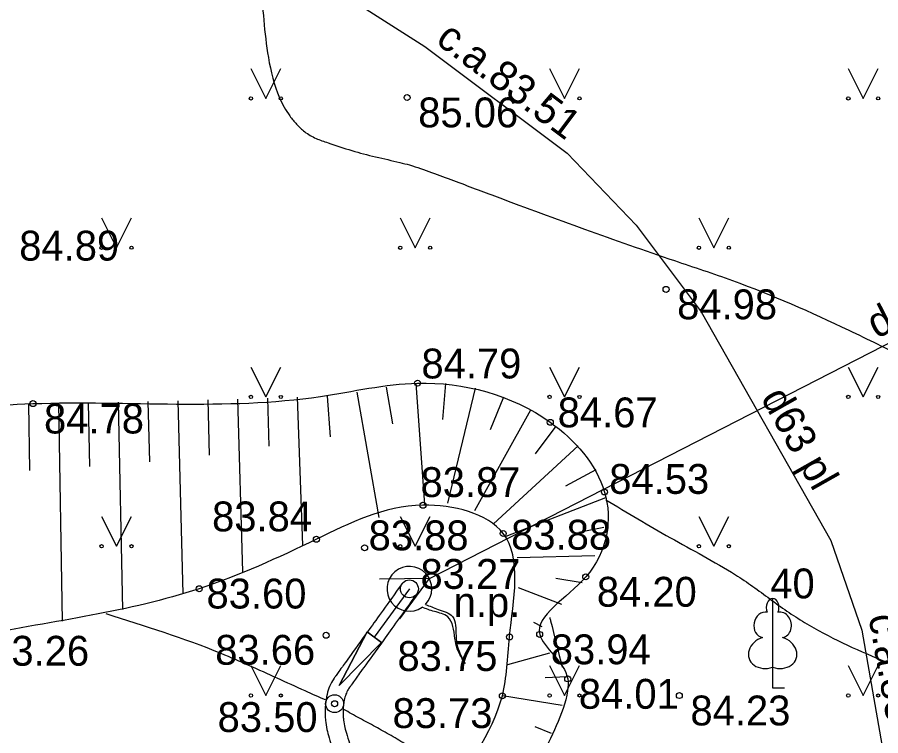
# Model space of a CAD drawing. Extents: x 576692 to 577659, y 273254 to 273799.
# Drawn here: x 576845.84 to 576860.29, y 273619.33 to 273631.36 of the extents above; entities that cross this region are included whole.
import ezdxf

# ---------------------------------------------------------------- set-up
doc = ezdxf.new("R2010")
doc.units = 0
for name, color, linetype in [('APGR_SARK_####_####_#', 7, 'Continuous'), ('BUVE_EKAS_ADRS_TKST_#', 7, 'Continuous'), ('ELEK_STTP_####_TKST_#', 7, 'Continuous'), ('GAZE_ELEM_####_####_#', 7, 'Continuous'), ('GAZE_VADP_VSP2_TKST_#', 7, 'Continuous'), ('GEOD_ELEM_####_TKST_#', 7, 'Continuous'), ('GEOD_SITP_####_TKST_#', 7, 'Continuous'), ('HIDT_REZV_####_TKST_#', 7, 'Continuous'), ('Level 50', 7, 'Continuous'), ('LKAN_ELEM_PAST_TKST_#', 7, 'Continuous'), ('LKAN_VADP_PAST_####_I', 7, 'Continuous'), ('NORB_ZOGS_ZSTP_####_#', 7, 'Continuous'), ('RELJ_ELEM_####_####_#', 7, 'Continuous'), ('SAKT_ELEM_####_####_#', 7, 'Continuous'), ('TERT_IZMT_####_TKST_#', 7, 'Continuous'), ('UDTK_VADP_UDEN_####_#', 7, 'Continuous')]:
    doc.layers.add(name, color=color, linetype=linetype)

msp = doc.modelspace()

# ---------------------------------------------------------------- linework, layer by layer
at = {"layer": 'BUVE_EKAS_ADRS_TKST_#'}
for p, q in [((576852.402, 273621.786), (576851.815, 273620.976)), ((576852.614, 273621.477), (576852.614, 273621.477)), ((576852.614, 273621.477), (576852.614, 273621.477)), ((576851.228, 273620.167), (576851.694, 273621.065)), ((576851.694, 273621.065), (576851.936, 273620.888)), ((576851.936, 273620.888), (576851.228, 273620.167))]:
    msp.add_line(p, q, dxfattribs=at)
msp.add_lwpolyline([(576851.815, 273620.976), (576851.694, 273621.065), (576851.228, 273620.167), (576851.936, 273620.888), (576851.815, 273620.976)], dxfattribs=at)
for centre in [(576852.402, 273621.786), (576851.15, 273619.863)]:
    msp.add_circle(centre, 0.15, dxfattribs=at)
msp.add_arc((576852.402, 273621.786), 0.375, 316.079, 304.6674, dxfattribs=at)
for points in [[(576852.671, 273621.525), (576852.885, 273621.443), (576853.124, 273621.323), (576853.183, 273620.998), (576853.209, 273620.815), (576853.337, 273620.537)], [(576853.337, 273620.537), (576853.204, 273620.783), (576853.165, 273620.957), (576853.044, 273621.317), (576852.821, 273621.407), (576852.614, 273621.477)]]:
    msp.add_spline(points, degree=3, dxfattribs=at)
at = {"layer": 'GAZE_ELEM_####_####_#'}
for p, q in [((576852.013, 273625.165), (576852.122, 273624.552)), ((576852.509, 273625.229), (576852.656, 273623.192)), ((576853.008, 273625.226), (576852.957, 273624.625)), ((576853.501, 273625.147), (576853.039, 273623.222)), ((576850.525, 273624.995), (576850.61, 273622.52)), ((576851.025, 273625.015), (576851.076, 273624.334)), ((576851.521, 273625.078), (576851.893, 273622.982)), ((576853.977, 273624.994), (576853.756, 273624.452)), ((576846.027, 273624.887), (576846.041, 273623.767)), ((576846.527, 273624.895), (576846.588, 273621.244)), ((576847.027, 273624.904), (576847.047, 273623.834)), ((576847.526, 273624.914), (576847.598, 273621.44)), ((576848.026, 273624.925), (576848.049, 273623.915)), ((576848.526, 273624.937), (576848.61, 273621.701)), ((576849.026, 273624.95), (576849.05, 273624.025)), ((576849.526, 273624.964), (576849.607, 273622.073)), ((576850.026, 273624.979), (576850.051, 273624.175)), ((576854.428, 273624.779), (576853.493, 273623.092)), ((576854.851, 273624.513), (576854.509, 273624.045)), ((576855.227, 273624.184), (576853.809, 273622.875)), ((576855.521, 273623.781), (576855.013, 273623.504)), ((576855.687, 273623.312), (576854.015, 273622.664)), ((576855.657, 273622.816), (576855.236, 273622.729)), ((576855.507, 273622.339), (576854.209, 273622.304)), ((576855.296, 273621.887), (576854.855, 273621.961)), ((576854.953, 273621.525), (576854.231, 273621.801)), ((576854.626, 273621.149), (576854.483, 273621.223)), ((576854.747, 273620.709), (576854.042, 273620.511)), ((576855.046, 273620.315), (576854.677, 273620.295)), ((576854.959, 273619.833), (576853.958, 273619.995)), ((576854.781, 273619.366), (576854.507, 273619.473))]:
    msp.add_line(p, q, dxfattribs=at)
msp.add_spline([(576832.752, 273667.765), (576832.509, 273663.16), (576832.58, 273657.617), (576832.99, 273656.888), (576834.178, 273656.214), (576834.728, 273652.581), (576835.768, 273647.802), (576835.442, 273646.054), (576836.91, 273644.618), (576839.764, 273638.662), (576839.933, 273637.528), (576840.475, 273632.274), (576842.148, 273628.271), (576842.73, 273626.244), (576843.067, 273625.31), (576843.946, 273624.925), (576846.1, 273624.888), (576850.915, 273625.009), (576852.538, 273625.231), (576854.761, 273624.575), (576855.668, 273623.408), (576855.354, 273621.987), (576854.583, 273621.023), (576855.053, 273620.278), (576855.05, 273620.08), (576854.604, 273618.921), (576854.165, 273617.889), (576853.774, 273617.488), (576853.674, 273617.252), (576853.77, 273616.967), (576854.827, 273616.356), (576854.95, 273616.221), (576855.722, 273614.848), (576857.549, 273612.349), (576858.206, 273610.078), (576857.63, 273607.292), (576856.966, 273605.786), (576854.948, 273601.016)], degree=3, dxfattribs=at)
at = {"layer": 'GAZE_VADP_VSP2_TKST_#'}
msp.add_lwpolyline([(576836.372, 273653.396), (576836.519, 273652.953), (576837.582, 273650.133), (576837.906, 273649.009), (576838.095, 273648.207), (576839.874, 273643.493), (576841.093, 273641.261), (576843.166, 273638.464), (576845.597, 273635.684), (576846.78, 273634.715), (576850.695, 273632.125), (576852.662, 273630.867), (576855.046, 273629.082), (576856.199, 273627.876), (576857.289, 273626.424), (576859.457, 273622.595), (576859.975, 273621.094), (576860.513, 273618.031), (576860.503, 273617.465), (576860.358, 273616.452), (576860.419, 273615.51), (576860.941, 273611.653), (576861.574, 273601.614), (576861.576, 273595.267)], dxfattribs=at)
at = {"layer": 'GEOD_ELEM_####_TKST_#'}
msp.add_spline([(576854.751, 273621.305), (576854.765, 273621.25), (576854.96, 273620.473)], degree=3, dxfattribs=at)
at = {"layer": 'GEOD_SITP_####_TKST_#'}
for points in [[(576836.737, 273653.507), (576837.199, 273653.071), (576838.168, 273651.964), (576839.276, 273650.389), (576839.675, 273649.775), (576840.068, 273649.157), (576840.874, 273647.935), (576842.937, 273645.043), (576843.644, 273644.077), (576844.358, 273643.116), (576845.071, 273642.154), (576845.776, 273641.185), (576846.532, 273639.939), (576848.959, 273635.068), (576849.467, 273633.911), (576849.494, 273633.87), (576849.54, 273633.844), (576849.669, 273633.76), (576849.716, 273633.696), (576849.75, 273633.628), (576849.789, 273633.484), (576849.818, 273633.184), (576849.885, 273632.56), (576849.923, 273631.934), (576849.964, 273631.308), (576850.042, 273630.684), (576850.228, 273630.011), (576850.401, 273629.706), (576850.514, 273629.568), (576850.649, 273629.442), (576850.839, 273629.33), (576851.04, 273629.256), (576851.437, 273629.127), (576852.241, 273628.927), (576852.405, 273628.885), (576852.774, 273628.757), (576853.14, 273628.623), (576853.871, 273628.35), (576855.336, 273627.811), (576856.838, 273627.284), (576857.811, 273626.95), (576859.757, 273626.119), (576860.71, 273625.654), (576861.662, 273625.19), (576862.208, 273624.916), (576862.747, 273624.63), (576863.288, 273624.343), (576863.84, 273624.071), (576864.734, 273623.812), (576865.684, 273623.739), (576866.647, 273623.686), (576867.118, 273623.618), (576867.35, 273623.56), (576867.582, 273623.491), (576867.793, 273623.35), (576869.286, 273620.101), (576869.949, 273618.673), (576870.065, 273618.383)], [(576855.69, 273623.279), (576856.771, 273622.643), (576857.319, 273622.34), (576857.859, 273622.023), (576858.151, 273621.827), (576858.436, 273621.619), (576858.722, 273621.414), (576859.019, 273621.223), (576860.313, 273620.593), (576861.378, 273620.176), (576862.149, 273619.833), (576862.903, 273619.459), (576863.642, 273619.051), (576864.37, 273618.606), (576864.715, 273618.279), (576865.665, 273616.764), (576866.071, 273615.581), (576866.112, 273615.391), (576866.295, 273615.092), (576866.625, 273614.961), (576867.386, 273614.691), (576867.79, 273614.462), (576868.144, 273614.156), (576868.694, 273613.398)], [(576850.996, 273619.925), (576850.659, 273620.076), (576850.191, 273620.288), (576849.253, 273620.702), (576847.324, 273621.365)], [(576853.147, 273618.43), (576852.951, 273618.676), (576852.725, 273618.9), (576852.605, 273618.996), (576852.483, 273619.087), (576852.357, 273619.172), (576852.228, 273619.252), (576851.965, 273619.403), (576851.699, 273619.548), (576851.434, 273619.693), (576851.305, 273619.766)]]:
    msp.add_spline(points, degree=3, dxfattribs=at)
at = {"layer": 'Level 50'}
msp.add_lwpolyline([(576852.738, 273621.958), (576869.063, 273630.326), (576880.368, 273635.749)], dxfattribs=at)
at = {"layer": 'LKAN_ELEM_PAST_TKST_#'}
for p, q in [((576849.75, 273630.5), (576850, 273630)), ((576850, 273630), (576850.25, 273630.5)), ((576854.75, 273630.5), (576855, 273630)), ((576855, 273630), (576855.25, 273630.5)), ((576859.75, 273630.5), (576860, 273630)), ((576860, 273630), (576860.25, 273630.5)), ((576847.25, 273628), (576847.5, 273627.5)), ((576847.5, 273627.5), (576847.75, 273628)), ((576852.25, 273628), (576852.5, 273627.5)), ((576852.5, 273627.5), (576852.75, 273628)), ((576857.25, 273628), (576857.5, 273627.5)), ((576857.5, 273627.5), (576857.75, 273628)), ((576849.75, 273625.5), (576850, 273625)), ((576850, 273625), (576850.25, 273625.5)), ((576854.75, 273625.5), (576855, 273625)), ((576855, 273625), (576855.25, 273625.5)), ((576859.75, 273625.5), (576860, 273625)), ((576860, 273625), (576860.25, 273625.5)), ((576847.25, 273623), (576847.5, 273622.5)), ((576847.5, 273622.5), (576847.75, 273623)), ((576852.25, 273623), (576852.5, 273622.5)), ((576852.5, 273622.5), (576852.75, 273623)), ((576857.25, 273623), (576857.5, 273622.5)), ((576857.5, 273622.5), (576857.75, 273623)), ((576849.75, 273620.5), (576850, 273620)), ((576850, 273620), (576850.25, 273620.5)), ((576854.75, 273620.5), (576855, 273620)), ((576855, 273620), (576855.25, 273620.5)), ((576858.483, 273620.474), (576858.483, 273620.127)), ((576859.75, 273620.5), (576860, 273620)), ((576860, 273620), (576860.25, 273620.5)), ((576858.483, 273620.127), (576858.683, 273620.127))]:
    msp.add_line(p, q, dxfattribs=at)
for points in [[(576858.483, 273621.627), (576858.483, 273620.474)], [(576858.573, 273621.395), (576858.572, 273621.396)]]:
    msp.add_lwpolyline(points, dxfattribs=at)
for centre, radius in [((576849.75, 273630), 0.028), ((576850.25, 273630), 0.0263), ((576854.75, 273630), 0.028), ((576855.25, 273630), 0.0263), ((576859.75, 273630), 0.028), ((576860.25, 273630), 0.0263), ((576847.25, 273627.5), 0.028), ((576847.75, 273627.5), 0.0263), ((576852.25, 273627.5), 0.028), ((576852.75, 273627.5), 0.0263), ((576857.25, 273627.5), 0.028), ((576857.75, 273627.5), 0.0263), ((576849.75, 273625), 0.028), ((576850.25, 273625), 0.0263), ((576854.75, 273625), 0.028), ((576855.25, 273625), 0.0263), ((576859.75, 273625), 0.028), ((576860.25, 273625), 0.0263), ((576847.25, 273622.5), 0.028), ((576847.75, 273622.5), 0.0263), ((576852.25, 273622.5), 0.028), ((576852.75, 273622.5), 0.0263), ((576857.25, 273622.5), 0.028), ((576857.75, 273622.5), 0.0263), ((576849.75, 273620), 0.028), ((576850.25, 273620), 0.0263), ((576854.75, 273620), 0.028), ((576855.25, 273620), 0.0263), ((576859.75, 273620), 0.028), ((576860.25, 273620), 0.0263)]:
    msp.add_circle(centre, radius, dxfattribs=at)
for centre, major_axis, ratio, start_param, end_param in [((576858.483, 273621.477), (0, -0.15), 0.707107, 3.14537, 5.287485), ((576858.483, 273621.477), (0, -0.15), 0.707107, 0.995701, 3.137816), ((576858.355, 273621.182), (-0.039, -0.212), 0.861323, 3.141593, 6.283185), ((576858.611, 273621.182), (0.039, -0.212), 0.861323, 0, 3.141593), ((576858.393, 273620.72), (0.307, 0.095), 0.814445, 1.570796, 4.752015), ((576858.573, 273620.72), (-0.307, 0.095), 0.814445, 1.531171, 4.712389)]:
    msp.add_ellipse(centre, major_axis=major_axis, ratio=ratio, start_param=start_param, end_param=end_param, dxfattribs=at)
at = {"layer": 'LKAN_VADP_PAST_####_I'}
msp.add_spline([(576812.842, 273665.824), (576812.811, 273665.743), (576812.814, 273665.69), (576812.851, 273665.627), (576812.986, 273665.49), (576814.774, 273663.674), (576815.389, 273662.702), (576815.866, 273661.966), (576816.7, 273660.402), (576817.524, 273658.924), (576817.855, 273658.352), (576818.596, 273657.416), (576819.8, 273656.007), (576821.141, 273654.684), (576822.497, 273653.371), (576823.874, 273652.107), (576824.573, 273651.255), (576825.95, 273649.694), (576826.971, 273648.461), (576827.47, 273647.902), (576827.903, 273647.372), (576828.575, 273646.001), (576828.884, 273644.971), (576829.158, 273643.944), (576829.304, 273643.361), (576829.471, 273642.524), (576829.32, 273641.873), (576829.119, 273641.091), (576828.921, 273640.069), (576828.875, 273639.626), (576828.835, 273639.304), (576828.849, 273638.281), (576829.046, 273636.949), (576829.801, 273634.584), (576830.167, 273633.657), (576830.692, 273632.653), (576831.781, 273630.74), (576832.922, 273628.899), (576834.187, 273627.04), (576835.095, 273625.631), (576836.095, 273624.213), (576837.098, 273622.801), (576838.263, 273621.273), (576838.65, 273620.304), (576838.81, 273619.863), (576839.313, 273618.25), (576839.984, 273616.65), (576840.504, 273615.889), (576840.765, 273615.631), (576841.015, 273615.399), (576841.324, 273615.171), (576842.389, 273614.438), (576843.595, 273614.11), (576844.811, 273614.066), (576846.015, 273614.188), (576847.455, 273614.453), (576848.892, 273614.904), (576849.184, 273615.13)], degree=3, dxfattribs=at)
for points in [[(576852.28, 273621.874), (576852.026, 273621.52), (576851.708, 273621.077), (576851.358, 273620.591), (576851.247, 273620.436), (576851.195, 273620.364), (576851.173, 273620.334), (576851.167, 273620.325), (576851.163, 273620.32), (576851.16, 273620.316), (576851.148, 273620.299), (576851.139, 273620.284), (576851.06, 273620.153), (576851.023, 273620.025), (576850.995, 273619.843), (576850.99, 273619.781), (576850.991, 273619.659), (576850.996, 273619.599), (576851.021, 273619.422), (576851.051, 273619.307), (576851.123, 273619.083), (576851.165, 273618.973), (576851.247, 273618.759), (576851.287, 273618.655), (576851.355, 273618.451), (576851.382, 273618.351), (576851.412, 273618.16), (576851.416, 273618.067), (576851.403, 273617.966), (576851.401, 273617.955), (576851.398, 273617.938), (576851.397, 273617.933), (576851.395, 273617.92), (576851.388, 273617.886), (576851.372, 273617.799), (576851.354, 273617.706), (576851.341, 273617.639), (576851.338, 273617.626)], [(576852.524, 273621.698), (576852.269, 273621.345), (576851.951, 273620.902), (576851.601, 273620.416), (576851.49, 273620.261), (576851.438, 273620.189), (576851.417, 273620.158), (576851.411, 273620.15), (576851.407, 273620.145), (576851.405, 273620.143), (576851.398, 273620.132), (576851.392, 273620.124), (576851.344, 273620.044), (576851.315, 273619.951), (576851.297, 273619.835), (576851.295, 273619.813), (576851.291, 273619.767), (576851.291, 273619.745), (576851.291, 273619.676), (576851.295, 273619.629), (576851.315, 273619.486), (576851.34, 273619.388), (576851.405, 273619.185), (576851.445, 273619.081), (576851.527, 273618.867), (576851.569, 273618.758), (576851.643, 273618.535), (576851.675, 273618.421), (576851.712, 273618.185), (576851.718, 273618.063), (576851.7, 273617.923), (576851.697, 273617.908), (576851.693, 273617.885), (576851.692, 273617.876), (576851.69, 273617.868), (576851.689, 273617.863), (576851.688, 273617.857), (576851.61, 273616.975)]]:
    msp.add_open_spline(points, degree=3, dxfattribs=at)
at = {"layer": 'RELJ_ELEM_####_####_#'}
for centre in [(576852.364, 273630.015), (576856.698, 273626.801), (576852.538, 273625.231), (576846.1, 273624.888), (576854.761, 273624.575), (576855.668, 273623.408), (576852.629, 273623.186), (576853.973, 273622.713), (576850.845, 273622.616), (576851.652, 273622.474), (576855.354, 273621.987), (576848.884, 273621.788), (576851.008, 273621.008), (576854.079, 273620.98), (576854.583, 273621.023), (576855.053, 273620.278), (576853.958, 273619.995), (576856.921, 273619.999), (576851.15, 273619.863)]:
    msp.add_circle(centre, 0.05, dxfattribs=at)
at = {"layer": 'SAKT_ELEM_####_####_#'}
msp.add_spline([(576854.948, 273601.016), (576854.301, 273604.39), (576855.034, 273607.594), (576855.939, 273609.37), (576855.48, 273610.601), (576855.167, 273611.215), (576854.024, 273612.547), (576853.371, 273614.86), (576852.758, 273616.2), (576853.019, 273618.136), (576853.958, 273619.995), (576854.079, 273620.98), (576853.973, 273622.713), (576852.629, 273623.186), (576850.845, 273622.616), (576848.884, 273621.788), (576845.182, 273620.999), (576842.758, 273620.833), (576840.549, 273622.928), (576838.693, 273626.289), (576836.368, 273633.613), (576835.78, 273638.891), (576834.899, 273640.23), (576833.405, 273646.669), (576832.452, 273651.751), (576831.801, 273653.923), (576830.268, 273654.02), (576829.902, 273654.785), (576830.578, 273656.811), (576829.943, 273658.248), (576830.972, 273664.323), (576832.752, 273667.765)], degree=3, dxfattribs=at)
at = {"layer": 'UDTK_VADP_UDEN_####_#'}
for p, q in [((576852.738, 273621.958), (576851.899, 273621.95)), ((576852.242, 273621.282), (576852.738, 273621.958))]:
    msp.add_line(p, q, dxfattribs=at)

# ---------------------------------------------------------------- texts
at = {"layer": 'APGR_SARK_####_####_#'}
msp.add_text(' 40', height=0.5, dxfattribs=at).set_placement((576858.258, 273621.627))
at = {"layer": 'ELEK_STTP_####_TKST_#'}
for s, rotation, p in [('c.a.83.51', 323.1763, (576852.822, 273630.935)), ('d63 pl', 299.5188, (576858.276, 273624.984)), ('c.a.83.40', 279.9621, (576860.086, 273621.327))]:
    msp.add_text(s, height=0.5, rotation=rotation, dxfattribs=at).set_placement(p)
at = {"layer": 'HIDT_REZV_####_TKST_#'}
for s, p in [(' 85.06', (576852.364, 273629.515)), (' 84.89', (576845.685, 273627.284)), (' 84.98', (576856.698, 273626.301)), (' 84.79', (576852.418, 273625.31)), (' 84.67', (576854.699, 273624.491)), (' 84.78', (576846.1, 273624.388)), (' 84.53', (576855.562, 273623.377)), (' 83.87', (576852.403, 273623.324)), (' 83.84', (576848.913, 273622.749)), (' 83.88', (576851.534, 273622.432)), (' 83.88', (576853.92, 273622.443)), (' 83.60', (576848.82, 273621.457)), (' 84.20', (576855.354, 273621.487)), (' 83.26', (576845.182, 273620.499)), (' 83.66', (576848.966, 273620.515)), (' 83.94', (576854.583, 273620.523)), (' 83.75', (576852.017, 273620.411)), (' 84.01', (576855.053, 273619.778)), (' 83.73', (576851.934, 273619.455)), (' 84.23', (576856.921, 273619.499))]:
    msp.add_text(s, height=0.5, dxfattribs=at).set_placement(p)
at = {"layer": 'NORB_ZOGS_ZSTP_####_#'}
for s, p in [(' 83.27', (576852.402, 273621.786)), (' 83.50', (576849.006, 273619.389))]:
    msp.add_text(s, height=0.5, dxfattribs=at).set_placement(p)
at = {"layer": 'TERT_IZMT_####_TKST_#'}
msp.add_text('d160 pl', height=0.5, rotation=27.1385, dxfattribs=at).set_placement((576860.224, 273625.968))
msp.add_text('n.p.', height=0.5, dxfattribs=at).set_placement((576853.143, 273621.315))

doc.saveas('drawing.dxf')
